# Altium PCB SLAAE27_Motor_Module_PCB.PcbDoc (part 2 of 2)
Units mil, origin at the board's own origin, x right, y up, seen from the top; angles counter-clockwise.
Board outline 2500 x 2000 mil, 4 copper layers (L1-Top Layer, L2-GND, L3-PWR, L4-Bottom Layer), stack 61.634 mil thick; 168 components, 85 nets, 418 pads, 206 vias.
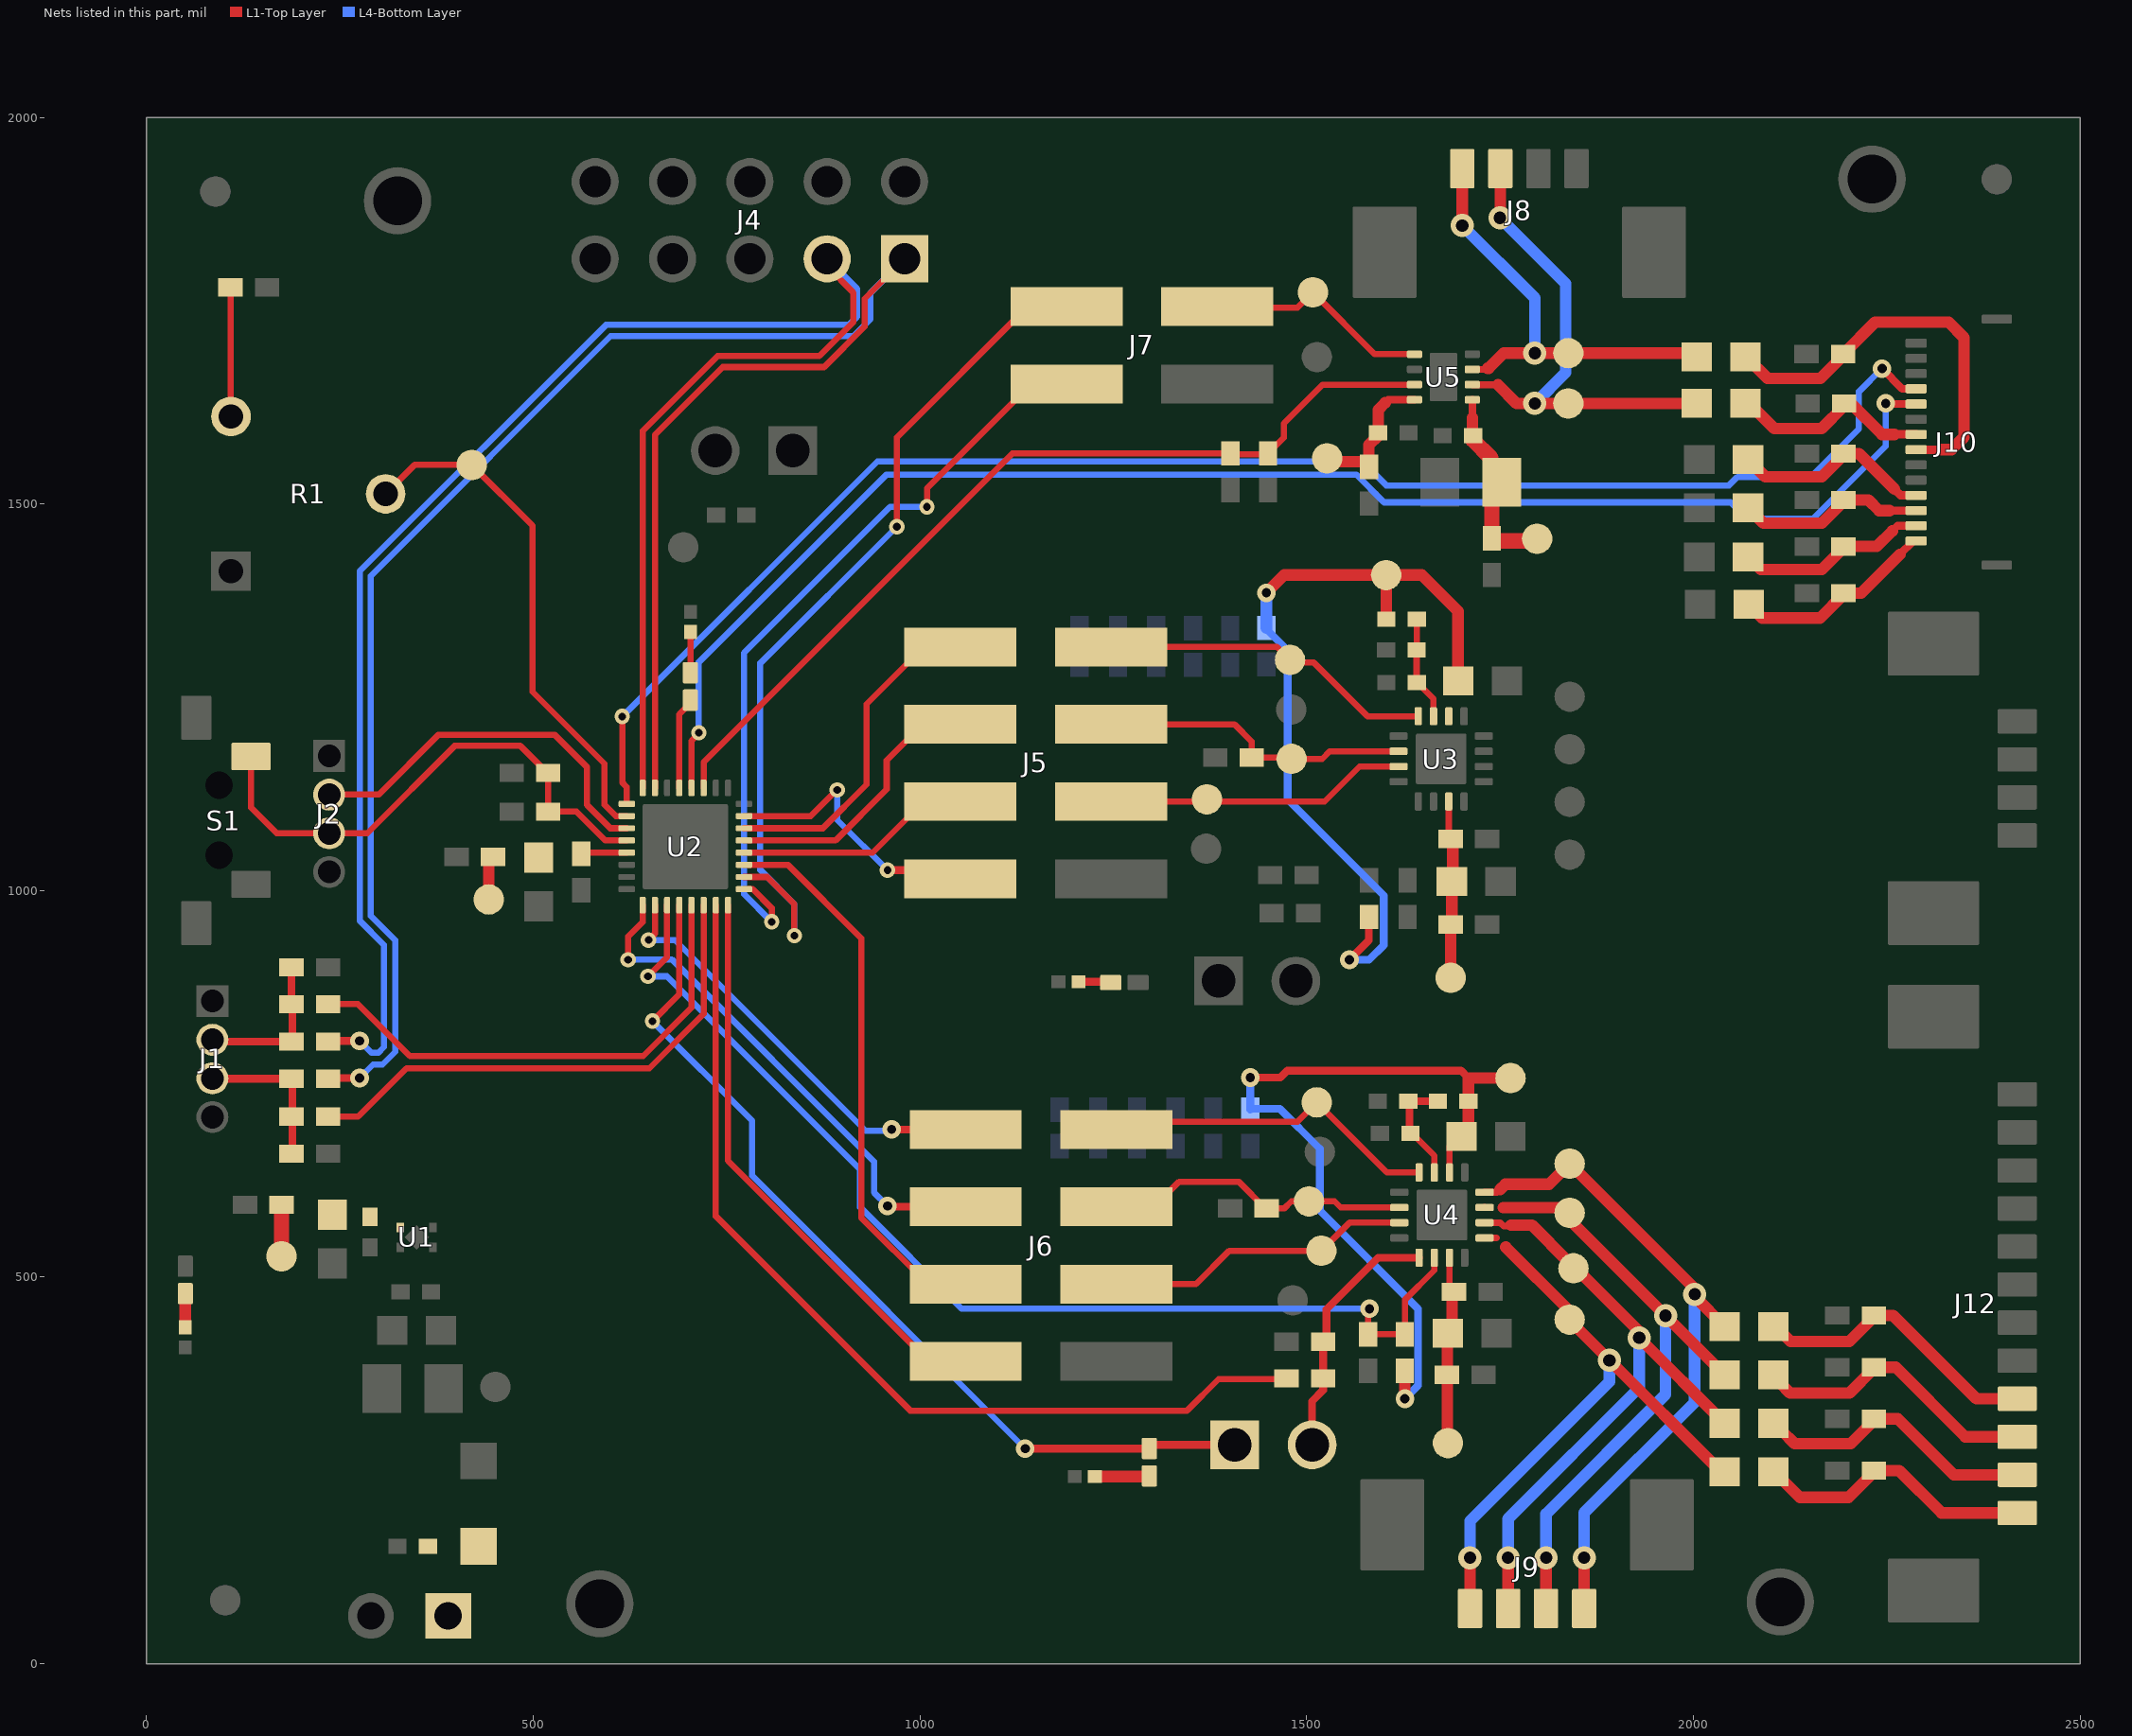
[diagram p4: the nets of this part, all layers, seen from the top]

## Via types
v1: diameter 24, hole 12, L1-Top Layer to L4-Bottom Layer, tented both sides, 151 vias
v2: diameter 30, hole 16, L1-Top Layer to L4-Bottom Layer, tented both sides, 20 vias
v3: diameter 20, hole 10, L1-Top Layer to L4-Bottom Layer, tented both sides, 18 vias
v4: diameter 19.68, hole 7.87, L1-Top Layer to L4-Bottom Layer, 17 vias

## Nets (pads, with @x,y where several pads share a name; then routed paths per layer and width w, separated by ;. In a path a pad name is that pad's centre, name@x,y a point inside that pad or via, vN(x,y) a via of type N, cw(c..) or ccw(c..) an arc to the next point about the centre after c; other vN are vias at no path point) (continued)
IN2/ENBL: IN2/ENBL.1 J7.3 U5.5 | length 319.4
  L1-Top Layer w8: J7.3@1363.44,1749 1368.44,1754 1488.23,1754 IN2/ENBL.1@1508,1773.77 1588.09,1693.67 U5.5@1639.4,1693.67
IRIS-M-A-N: IRIS-M-A-N.1 J8.1 L2.1 U5.3 | length 575.8
  L1-Top Layer w9: U5.3@1714.2,1673.99 1733.85,1673.99
  L1-Top Layer w15: v2(1701.18,1860) J8.1@1701.18,1933.74 ; 1733.85,1675.44 1735.3,1675.44 1754.86,1695 v2(1795,1695) IRIS-M-A-N.1@1838.3,1695 L2.1@2004.26,1695
  L4-Bottom Layer w15: v2(1701.18,1860) 1795,1766.18 v2(1795,1695)
IRIS-M-A-P: IRIS-M-A-P.1 J8.2 L1.1 U5.2 | length 655.7
  L1-Top Layer w9: U5.2@1714.2,1654.3 1714.39,1654.12 1747.27,1654.12
  L1-Top Layer w15: 1747.27,1654.12 1771.39,1630 v2(1795,1630) IRIS-M-A-P.1@1838.3,1630 L1.1@2004.26,1630 ; v2(1750,1870) 1750.39,1870.39 J8.2@1750.39,1933.74
  L4-Bottom Layer w15: v2(1750,1870) 1834.91,1785.09 1834.91,1669.91 v2(1795,1630)
IRIS_nSLEEP: R18.2 R20.1 U2.27 U5.7 | length 1165.5
  L1-Top Layer w8: U2.27@720.22,1132.65 720.22,1165.95 1119.52,1565.24 R18.2@1401.41,1565.24 ; R18.2@1406.97,1564.19 R20.1@1455.56,1564.19 ; R20.1@1450,1565.24 1470.5,1585.74 1470.5,1604.12 1520.68,1654.3 U5.7@1639.4,1654.3
M0_0: J5.7 M0_0.1 U3.8 | length 456.8
  L1-Top Layer w8: J5.7@1247,1315 1461.61,1315 M0_0.1@1478.42,1298.19 ; M0_0.1@1478.42,1294.67 1509.33,1294.67 1578.63,1225.37 U3.8@1644.36,1225.37
  L1-Top Layer w10: J5.7@1230,1314 J5.7@1246.81,1297.19
M0_1: J6.7 M0_1.1 U4.8 | length 444.2
  L1-Top Layer w8: J6.7@1254,690.87 1264.13,701 1488,701 M0_1.1@1513,726 ; M0_1.1@1512.5,726.5 M0_1.1@1513,726 ; U4.8@1645.35,635.28 1603.72,635.28 M0_1.1@1513,726
M1_0: J5.5 M1_0.1 R17.2 U3.10 | length 410.7
  L1-Top Layer w8: J5.5@1247,1215 1406.51,1215 1428.93,1192.58 R17.2@1428.93,1171.87 1477.38,1171.87 1479.7,1169.56 M1_0.1@1480.4,1170.25 1520.13,1170.25 1529.97,1180.1 U3.10@1618.77,1180.1 ; M1_0.1@1485,1182.65 M1_0.1@1487.55,1180.1
M1_1: J6.5 M1_1.1 R19.2 U4.10 | length 399.3
  L1-Top Layer w8: J6.5@1254,590.87 1302.59,590.87 1335.11,623.4 1412.11,623.4 R19.2@1446.78,588.73 ; R19.2@1448.26,588.73 1470.99,588.73 1480.27,598 M1_1.1@1503,598 1536,598 1544,590 U4.10@1619.76,590
MSP_DIR_0: J5.2 U2.23 | length 364
  L1-Top Layer w8: U2.23@772.39,1096.23 858.73,1096.23 892.5,1130 v3(893,1130)
  L1-Top Layer w10: v3(958,1026.31) 1040.81,1026.31 J5.2@1052.12,1015
  L4-Bottom Layer w8: v3(893,1130) 893,1091.31 v3(958,1026.31)
MSP_DIR_1: J6.2 U2.16 | length 745.5
  L1-Top Layer w8: U2.16@751.72,981.07 751.72,650.47 1011.31,390.87 J6.2@1059.12,390.87
MSP_IN1/PHASE: J7.2 U2.17 | length 1001.6
  L1-Top Layer w8: U2.17@772.39,1001.74 783.69,1001.74 808.32,977.12 v3(808.32,959.49) ; v3(1009,1496.31) 1009,1520 1144.18,1655.18 J7.2@1189.56,1655.18
  L4-Bottom Layer w8: v3(808.32,959.49) 772.39,995.42 772.39,1307.39 961.31,1496.31 v3(1009,1496.31)
MSP_IN2/ENBL: J7.4 U2.18 | length 1146.1
  L1-Top Layer w8: U2.18@772.39,1017.49 802.51,1017.49 837.58,982.42 v3(837.58,941.52) ; v3(970,1470.57) 970,1586 1139.18,1755.18 J7.4@1189.56,1755.18
  L4-Bottom Layer w8: v3(837.58,941.52) 837.58,982.42 793.45,1026.55 793.45,1294.02 v3(970,1470.57)
MSP_M0_0: J5.8 U2.22 | length 437.8
  L1-Top Layer w8: U2.22@772.39,1080.48 874.42,1080.48 931,1137.07 931,1241 1005,1315 J5.8@1052.12,1315
MSP_M0_1: J6.8 U2.10 | length 559.5
  L1-Top Layer w8: v3(649,935.93) 657.23,944.16 U2.10@657.23,981.07
  L1-Top Layer w10: v1(963.41,691.15) 963.69,690.87 J6.8@1059.12,690.87
  L4-Bottom Layer w8: v3(649,935.93) 683.07,935.93 929.68,689.32 v1@962,689.32
MSP_M1_0: J5.6 U2.21 | length 363.9
  L1-Top Layer w8: U2.21@772.39,1064.73 890.73,1064.73 956.92,1130.92 956.92,1168.28 1003.63,1215 J5.6@1052.12,1215
MSP_M1_1: J6.6 U2.9 | length 671.2
  L1-Top Layer w8: v3(622.57,910.43) 622.57,940.43 641.48,959.35 U2.9@641.48,981.07
  L1-Top Layer w10: v1(958,592) 959.13,590.87 J6.6@1059.12,590.87
  L4-Bottom Layer w8: v3(622.57,910.43) 623.01,910.87 679.13,910.87 940.5,649.5 940.5,609.5 v1(958,592)
MSP_STEP_0: J5.4 U2.20 | length 307.1
  L1-Top Layer w8: U2.20@772.39,1048.99 938.99,1048.99 1005,1115 J5.4@1052.12,1115
MSP_STEP_1: J6.4 U2.19 | length 723.2
  L1-Top Layer w8: U2.19@772.39,1033.24 829.05,1033.24 924,938.29 924,576.68 1009.81,490.87 J6.4@1059.12,490.87
Net3.3V_1: 3.3V.1 C1.1 C3.2 R4.1 U1.1 | length 68.3
  L1-Top Layer w20: 3.3V.1@174.47,526.92 174.47,589.65 R4.1@178.41,593.58
Net3.3V_MCU_1: 3.3V_MCU.1 C8.1 C9.2 R11.2 U2.5 | length 121.1
  L1-Top Layer w8: C9.2@557,1048.99 U2.5@620.81,1048.99
  L1-Top Layer w15: 3.3V_MCU.1@442.38,988.38 442.38,1037.76 R11.2@448,1043.38
NetC5_2: C5.2 D2.2 J3.1
NetC12_2: C12.2 R25.2 U5.8 VCC.1 | length 191.9
  L1-Top Layer w10: 1601.53,1630.7 1605.45,1634.62 U5.8@1639.4,1634.62
  L1-Top Layer w15: VCC.1@1525,1548.43 1531.19,1554.62 1573.72,1554.62 R25.2@1580.46,1547.88 1580.46,1576.27 1592.48,1588.28 1592.48,1621.64 1601.53,1630.7
NetC13_2: C13.2 R26.1 R31.2 U4.7 | length 149.5
  L1-Top Layer w8: C13.2@1633.54,688.49 1665.04,656.99 U4.7@1665.04,635.28
  L1-Top Layer w10: C13.2@1632.64,687.59 1633.54,688.49 C13.2@1634.37,689.32 ; C13.2@1638.02,685.67 1636.05,687.64 C13.2@1634.37,689.32 ; R31.2@1669.71,727.36 1632.82,727.36 1632.82,690.87 C13.2@1634.37,689.32
NetC14_2: C14.2 R27.1 R28.2 U3.7 | length 135.3
  L1-Top Layer w8: R28.2@1642.39,1351.14 1642.39,1311.3 R27.1@1642.14,1311.05 1642.14,1269.33 C14.2@1642.39,1269.07 1642.93,1269.07 1664.05,1247.95 U3.7@1664.05,1225.37
NetC15_1: C15.1 C18.2 R34.2 U5.1 VM_Iris.1 | length 254.1
  L1-Top Layer w10: C18.2@1714.2,1588.54 C18.2@1714.46,1588.28 ; 1714.2,1611.58 U5.1@1714.2,1634.62
  L1-Top Layer w15: C18.2@1714.2,1588.54 1714.2,1611.58
  L1-Top Layer w20: C18.2@1714.46,1588.28 1714.46,1583.23 1738.2,1559.48 1738.2,1510.64 1739.39,1509.45 R34.2@1739.39,1455.41 R34.2@1739.39,1452.05 ; R34.2@1738.01,1452.05 R34.2@1739.39,1452.05 ; VM_Iris.1@1797.92,1455 1794.96,1452.05 R34.2@1739.39,1452.05
NetC16_1: C16.1 C20.1 R32.2 U4.15 VM_TM.1 | length 243.7
  L1-Top Layer w8: C20.1@1684.72,477.75 U4.15@1684.72,525.04
  L1-Top Layer w15: VM_TM.1@1682.7,285.3 1681.78,286.23 1681.78,424.21 1688.15,430.59 C20.1@1688.15,478.69
NetC17_1: C17.1 C19.1 R33.2 U3.15 VM_Focus.1 | length 220.2
  L1-Top Layer w8: C19.1@1683.73,1076.34 U3.15@1683.73,1115.14
  L1-Top Layer w15: VM_Focus.1@1686.14,887.07 R33.2@1686.14,956.09 1687.71,957.67 C17.1@1687.71,1011.72 ; C17.1@1689.01,1011.72 1689.01,1064.13 C19.1@1691.61,1066.72
NetC23_1: C23.1 J10.7 L2.2 | length 530
  L1-Top Layer w11: J10.7@2288.07,1570.16 2320,1570.16
  L1-Top Layer w15: L2.2@2068.72,1690 2068.72,1689.46 2095.91,1662.27 2164.27,1662.27 2193.62,1691.62 C23.1@2193.62,1693.67 2234.95,1735 2330,1735 2350,1715 2350,1586.34 2333.82,1570.16 2320,1570.16
NetC24_2: C24.2 J10.1 L6.2 | length 264.4
  L1-Top Layer w10: 2267.03,1434.71 2284.37,1452.05 J10.1@2288.07,1452.05
  L1-Top Layer w15: L6.2@2071.5,1370 2089.2,1352.3 2163.73,1352.3 C24.2@2194,1382.57 ; C24.2@2194,1384.63 2216.95,1384.63 2267.03,1434.71
NetC25_2: C25.2 J10.2 L3.2 | length 248.9
  L1-Top Layer w10: 2257.2,1465 2263.93,1471.73 J10.2@2288.07,1471.73
  L1-Top Layer w15: L3.2@2070.7,1431.55 2087.24,1415 2166.06,1415 2194,1442.94 C25.2@2194,1445 2237.2,1445 2257.2,1465
NetC26_2: C26.2 J10.3 L4.2 | length 240
  L1-Top Layer w10: 2258.58,1491.42 J10.3@2288.07,1491.42
  L1-Top Layer w15: L4.2@2070.7,1495 2090.7,1475 2166.06,1475 2194,1502.94 C26.2@2194,1505 2226.52,1505 2240.1,1491.42 2253.62,1491.42
NetC27_1: C27.1 J10.4 L5.2 | length 262.6
  L1-Top Layer w11: 2260,1519.12 2268.02,1511.1 J10.4@2288.07,1511.1
  L1-Top Layer w15: L5.2@2070.7,1557.36 2093.05,1535 2166.06,1535 2194,1562.94 C27.1@2194,1565 2214.12,1565 2260,1519.12
NetC28_1: C28.1 J10.8 L1.2 | length 268.2
  L1-Top Layer w11: 2260,1589.84 J10.8@2288.07,1589.84
  L1-Top Layer w15: L1.2@2068.62,1635 2068.62,1633.37 2104.62,1597.37 2165.95,1597.37 2195,1626.42 C28.1@2195,1630 2203.81,1630 2243.97,1589.84 2260,1589.84
NetC29_1: C29.1 J12.12 L7.2 | length 352.7
  L1-Top Layer w15: L7.2@2114.14,238.74 2137.86,215.03 2200.75,215.03 2233.3,247.57 C29.1@2233.3,249.63 2266.27,249.63 2320.87,195.03 J12.12@2418.9,195.03
NetC30_1: C30.1 J12.11 L8.2 | length 354.9
  L1-Top Layer w15: L8.2@2114.14,301.45 2130.96,284.63 2203.57,284.63 2235.5,316.56 2264.44,316.56 2336.76,244.24 J12.11@2418.9,244.24
NetC31_2: C31.2 J12.10 L9.2 | length 364
  L1-Top Layer w15: L9.2@2112.47,362.53 2125,350 2201.87,350 2233.3,381.43 C31.2@2233.3,383.49 2261.51,383.49 2351.55,293.45 J12.10@2418.9,293.45
NetC32_2: C32.2 J12.9 L10.2 | length 368.3
  L1-Top Layer w15: L10.2@2114.96,427.42 2125.83,416.55 2201.55,416.55 2233.3,448.3 C32.2@2233.3,450.42 2258.32,450.42 2366.07,342.66 J12.9@2418.9,342.66
NetD1_1: D1.1 R2.1 | length 43.5
  L1-Top Layer w15: R2.1@50,435 D1.1@50,478.54
NetD3_1: D3.1 R14.1 | length 50.7
  L1-Top Layer w8: D3.1@703.12,1282.17 R14.1@703.12,1332.83
NetD4_1: D4.1 R15.1 | length 42.9
  L1-Top Layer w10: R15.1@1204.99,882.05 1245.52,882.05 D4.1@1246.57,881 D4.1@1246.57,880.07
NetD5_1: D5.1 R16.1 | length 61.3
  L1-Top Layer w15: R16.1@1235,242.07 1291.82,242.07 D5.1@1295,238.89
NetJ1_2: J1.2 R8.2 R9.1 R10.1 | length 199.8
  L1-Top Layer w10: J1.2@85,807 87.5,804.5 R8.2@187.38,804.5 ; R10.1@187.38,900.5 187.38,853.98 188.38,852.98 R8.2@188.38,804.5
NetJ1_3: J1.3 R5.1 R6.1 R7.2 | length 199.6
  L1-Top Layer w10: J1.3@85,756.5 R7.2@187.38,756.5 ; R5.1@188.38,659.5 188.38,707.27 188.61,707.5 188.61,756.27 R7.2@188.38,756.5
NetR1_3: R1.3 R3.1 | length 167.3
  L1-Top Layer w8: R3.1@108.38,1780 108.38,1613.62 R1.3@109,1613
PI_EN: J10.10 U2.28 | length 1959.1
  L1-Top Layer w8: U2.28@704.48,1132.65 704.48,1193.52 714,1203.05 v3(714,1204)
  L1-Top Layer w10: v1(2248.7,1630) 2249.49,1629.21 J10.10@2288.07,1629.21
  L4-Bottom Layer w8: v3(714,1204) 714,1295.23 956.77,1538 1564.06,1538 1600.06,1502 2048,1502 2068.87,1481.13 2155.13,1481.13 2248.7,1574.7 v1(2248.7,1630)
PI_INT: D3.2 U2.29 | length 120
  L1-Top Layer w8: U2.29@688.73,1132.65 688.73,1227.85 703.12,1242.24 D3.2@703.12,1246.73
PI_OUT: J10.11 U2.1 | length 2039.6
  L1-Top Layer w8: v3(615,1225) 615,1139.68 620.81,1133.86 U2.1@620.81,1111.98
  L1-Top Layer w10: v1(2243.97,1675.03) 2270.1,1648.9 J10.11@2288.07,1648.9
  L4-Bottom Layer w8: v3(615,1225) 945,1555 1572,1555 1603,1524 2046,1524 2057,1535 2152,1535 2214.12,1597.12 2214.12,1645.18 v1(2243.97,1675.03)
RST: C7.1 J2.3 R12.1 S1.3 U2.4 | length 692.4
  L1-Top Layer w8: S1.3@135,1173.33 135,1107.31 168.31,1074 J2.3@236,1074 285.32,1074 398.32,1187 483.33,1187 518.33,1152 C7.1@519.24,1152 R12.1@519.24,1102 556,1102 593.27,1064.73 U2.4@620.81,1064.73
RXD: R6.2 U2.14 | length 681.4
  L1-Top Layer w8: R6.2@234.62,707.5 273.5,707.5 336,770 650,770 720.22,840.22 U2.14@720.22,981.07
SCL: J4.1 R7.1 U2.31 | length 2504.1
  L1-Top Layer w8: U2.31@657.23,1132.65 657.23,1589.23 745,1677 876,1677 928.5,1729.5 928.5,1765.5 J4.1@980,1817
  L1-Top Layer w10: R7.1@234.62,757.5 v1(275.38,757.5)
  L4-Bottom Layer w8: v1(275.38,757.5) 292.88,775 305,775 321.5,791.5 321.5,935.5 289.92,967.08 289.92,1406.92 600,1717 914,1717 936,1739 936,1773 J4.1@980,1817
SDA: J4.3 R8.1 U2.32 | length 2469.1
  L1-Top Layer w8: U2.32@641.48,1132.65 641.48,1594.48 738.5,1691.5 869.99,1691.5 914,1735.51 914,1773 880,1807 J4.3@880,1817
  L1-Top Layer w10: R8.1@234.62,805.5 v1(275.38,805.5)
  L4-Bottom Layer w8: v1(275.38,805.5) 290.88,790 299.49,790 307,797.51 307,929.49 275.42,961.07 275.42,1412.93 593.99,1731.5 907.99,1731.5 918.49,1742 918.49,1778.51 J4.3@880,1817
SPEED_REF: R1.2 SPEED_REF.1 U2.2 | length 672.5
  L1-Top Layer w8: R1.2@309,1513 346.47,1550.47 SPEED_REF.1@420.47,1550.47 499,1471.94 499,1257 592,1164 592,1110.92 606.69,1096.23 U2.2@620.81,1096.23
STEP_0: J5.3 STEP_0.1 U3.11 | length 390.6
  L1-Top Layer w8: J5.3@1247,1115 1523.03,1115 1568.44,1160.41 U3.11@1618.77,1160.41
STEP_1: J6.3 STEP_1.1 U4.11 | length 398.7
  L1-Top Layer w8: J6.3@1254,490.87 1356.87,490.87 1400,534 STEP_1.1@1519,534 1555.31,570.31 U4.11@1619.76,570.31
TEST: J2.2 U2.3 | length 495.7
  L1-Top Layer w8: J2.2@236,1124 300,1124 377.5,1201.5 527.5,1201.5 569.5,1159.5 569.5,1110.5 599.52,1080.48 U2.3@620.81,1080.48
TM_A_N: J9.2 L9.1 TM_A_N.1 U4.3 | length 826.3
  L1-Top Layer w9: U4.3@1730,590 U4.3@1730.19,589.81
  L1-Top Layer w15: 1754.2,589.91 1828.24,589.91 TM_A_N.1@1840,578.15 ; J9.2@1809.61,71.26 v2(1809.61,136.98) ; TM_A_N.1@1840,583.15 TM_A_N.1@1840,578.15 ; L9.1@2040.5,373.56 v2(1964.07,450) 1840,574.07 TM_A_N.1@1840,578.15
  L4-Bottom Layer w15: v2(1809.61,136.98) 1809.61,193.61 1964.07,348.07 v2(1964.07,450)
TM_A_P: J9.1 L10.1 TM_A_P.1 U4.4 | length 879.5
  L1-Top Layer w9: U4.4@1730,609.68 1746.03,609.68
  L1-Top Layer w15: 1750,613 1757,620 1813.3,620 TM_A_P.1@1840,646.7 2001.7,485 v2(2001.7,477.75) 2001.7,474.75 L10.1@2040.5,435.95 ; J9.1@1858.82,71.26 v2(1858.82,136.98)
  L4-Bottom Layer w15: v2(1858.82,136.98) 1858.82,195.17 2001.7,338.05 v2(2001.7,477.75)
TM_B_N: J9.4 L7.1 TM_B_N.1 U4.1 | length 808.9
  L1-Top Layer w9: U4.1@1730,550.63 1745.41,550.63
  L1-Top Layer w15: J9.4@1711.18,71.26 v2(1711.18,136.98) ; 1757.43,538.61 1840,456.04 TM_B_N.1@1840,445.06 1840,443.85 v2(1891.42,392.43) L7.1@2030,253.85
  L4-Bottom Layer w15: v2(1711.18,136.98) 1711.18,184.44 1891.42,364.68 v2(1891.42,392.43)
TM_B_P: J9.3 L8.1 TM_B_P.1 U4.2 | length 843.6
  L1-Top Layer w9: U4.2@1730,570.31 1750.33,570.31 1754.68,565.96 1764.13,565.96
  L1-Top Layer w15: J9.3@1760.39,71.26 v2(1760.39,136.98) ; 1764.13,567.03 1791.26,567.03 1838.7,519.59 1840,519.59 1930,429.59 v2(1930,421.31) L8.1@2040.5,310.81
  L4-Bottom Layer w15: v2(1760.39,136.98) 1760.39,187.32 1930,356.93 v2(1930,421.31)
TM_EN: R22.1 U2.15 | length 1268.7
  L1-Top Layer w8: U2.15@735.97,981.07 735.97,578.77 987.43,327.31 1345.31,327.31 1386,368 1475.38,368 R22.1@1475.38,374
TM_EN_nFAULT: C11.1 JP3.2 R22.2 U4.13 | length 330.4
  L1-Top Layer w10: JP3.2@1507,283 1507,339.26 1521.24,353.5 C11.1@1521.24,416.55 1525.57,420.87 1525.57,458.3 1592.31,525.04 U4.13@1645.35,525.04
TM_nFAULT: D5.2 JP3.1 U2.12 | length 1181.1
  L1-Top Layer w8: v3(654,831) 688.73,865.73 U2.12@688.73,981.07
  L1-Top Layer w10: v1(1136,278) D5.2@1288,278 ; D5.2@1295,283 JP3.1@1407,283
  L4-Bottom Layer w8: v3(654,831) 783,702 783,631 v1(1136,278)
TM_nSLEEP: R23.1 R29.2 U2.11 U4.14 | length 1432.6
  L1-Top Layer w8: v3(648.25,889) 672.98,913.73 U2.11@672.98,981.07 ; v1(1581.22,459) 1580,459 1579.32,458.32 R23.1@1579.32,425.98 R29.2@1626.94,425.98 ; R29.2@1626.94,432.36 1626.94,470.59 1665.04,508.69 U4.14@1665.04,525.04
  L4-Bottom Layer w8: v3(648.25,889) 672.82,889 922.63,639.19 922.63,590.37 1054,459 v1(1581.22,459)
TXD: R9.2 U2.13 | length 656.1
  L1-Top Layer w8: R9.2@234.62,852.98 273.35,852.98 340.33,786 642,786 704.48,848.48 U2.13@704.48,981.07
VDD0: C21.1 R24.1 R28.1 R35.2 U3.6 VDD0.1 | length 1070.6
  L1-Top Layer w10: v1(1555.31,910.43) 1580.46,935.58 R24.1@1580.46,965.9
  L1-Top Layer w15: v1(1448,1385) 1471,1408 VDD0.1@1595.54,1408 ; VDD0.1@1602.77,1408 VDD0.1@1595.54,1408 ; R28.1@1603.02,1351.14 1603.02,1400.52 VDD0.1@1595.54,1408 ; C21.1@1695.82,1270.98 1695.82,1361.07 1648.72,1408.17 1595.38,1408.17 VDD0.1@1595.54,1408
  L4-Bottom Layer w10: R35.2@1447.25,1338.88 1475.38,1310.75 1475.38,1117.58 1599.69,993.27 1599.69,929.47 1580.65,910.43 v1(1555.31,910.43)
  L4-Bottom Layer w15: R35.2@1448,1339.62 v1(1448,1385)
VDD1: C22.1 R29.1 R31.1 R36.2 U4.6 VDD1.1 | length 1048.3
  L1-Top Layer w8: U4.6@1684.72,635.28 1684.72,669.28 C22.1@1708.99,693.55
  L1-Top Layer w10: v1(1427,758) 1466,758 1475,767 1699.44,767 1709.08,757.36 ; R31.1@1708.99,727.26 R31.1@1709.08,727.36
  L1-Top Layer w15: v1(1626.94,342.66) R29.1@1626.94,378.74 ; C22.1@1708.99,693.55 R31.1@1708.99,727.26 ; R31.1@1709.08,727.36 1709.08,757.36 VDD1.1@1763.53,757.36
  L4-Bottom Layer w10: R36.2@1427,716.62 R36.2@1427,717.62 ; v1(1427,758) R36.2@1427,717.62 ; v1(1626.94,342.66) 1644,359.72 1644,459 1517,586 1517,666 1465.38,717.62 R36.2@1427,717.62
pads on no net: FID1.1 FID2.1 FID3.1 FID4.1 FID5.1 FID6.1 H1.0 H2.0 H3.0 H4.0 J4.4 J4.5 J4.6 J4.7 J4.8 J4.9 J8.3 J8.4 J10.5 J10.6 J10.9 J10.13 J10.14 J12.1 J12.7 LBL1.0 S1. U5.9@1676.8,1646.43 U5.9@1676.8,1681.86

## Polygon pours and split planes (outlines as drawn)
TM_EN_nFAULT on L1-Top Layer "L1-TOP_LAYER_TM_EN_NFAULT_P052" (solid, pour order 52): 1504.52,410.23 1504.52,352.44 1473.26,321.18 1473.26,259.81 1486.78,246.28 1534.15,246.28 1546,258.13 1546,410.68 1546,455.3 1600.35,509.65 1648.68,509.65 1653,513.97 1653,535 1649,539 1645,539.09 1591.09,539.09 1504.52,452.52
3.3V on L1-Top Layer "L1-TOP_LAYER_3.3V_P086" (solid, pour order 86): 1593.45,1515.9 1553.05,1516.04 1550.47,1518.62 1518.62,1518.62 1510.17,1510.17 1510.17,1444.21 1524.01,1430.37 1582.37,1430.37 1593.45,1441.45
3.3V on L1-Top Layer "L1-TOP_LAYER_3.3V_P084" (solid, pour order 84): 413.16,1060.05 379.05,1060.17 373.23,1066 340.16,1066 326.31,1052.15 326.3,981.49 337.1,970.69 399.39,970.69 413.16,984.47 413.16,1055.97
5V on L1-Top Layer "L1-TOP_LAYER_5V_P082" (solid, pour order 82): 1722.74,1427.42 1722.59,1386.47 1716.77,1380.64 1716.77,1364 1739.5,1341.27 1783.18,1341.27 1814.09,1372.18 1814.09,1406.03 1792.7,1427.42
5V on L1-Top Layer "L1-TOP_LAYER_5V_P080" (solid, pour order 80): 1718.1,970 1717.97,933.01 1715.25,930.3 1715.25,907.44 1736.99,885.69 1794.3,885.69 1809.3,900.7 1809.31,957.97 1797.27,970
5V on L1-Top Layer "L1-TOP_LAYER_5V_P078" (solid, pour order 78): 1711.95,386 1711.83,351.89 1706,346.07 1706,319.95 1719.26,306.69 1781.31,306.69 1802.23,327.62 1802.23,360.77 1777,386 1716.03,386
FOCUS_EN_nFAULT on L1-Top Layer "L1-TOP_LAYER_FOCUS_EN_NFAULT_P054" (solid, pour order 54): 1482.01,936.01 1454,908 1454,862.63 1470.63,846 1512,846 1525.5,859.5 1525.5,1002.5 1525.5,1025.89 1599.36,1099.75 1647.69,1099.75 1652.01,1104.07 1652.01,1125.1 1648.01,1129.1 1644.01,1129.19 1579.81,1129.19 1482.01,1031.38
Net3.3V_MCU_1 on L1-Top Layer "L1-TOP_LAYER_NET3.3V_MCU_1_P060" (solid, pour order 60): 628.86,1056 582.73,1056 566.83,1071.89 440.89,1071.89 420,1051 420,976 432,964 456,964 464.01,972.01 464.01,1008.01 475,1019 538,1019 550,1031 573,1031 586,1044 630,1044 632,1046 632,1052.86
GND on L1-Top Layer "L1-TOP_LAYER_GND_P062" (solid, pour order 62): 592.5,1039 570.5,1017 550,1017 533,1000 489,1000 475,986 475,914.23 494.09,895.14 529.59,895.14 542,907.55 542,950 582.5,990.5 582.5,1007.5 603,1028 626.86,1028 630,1031.14 630,1037 628,1039
VDD0 on L1-Top Layer "L1-TOP_LAYER_VDD0_P036" (solid, pour order 36): 1675,1212.23 1675,1288.27 1680.73,1294 1712.08,1294 1718.17,1287.9 1718.17,1252.05 1714.74,1248.62 1698.15,1248.62 1691.26,1241.72 1691.26,1213.49 1690,1212.23
GND on L1-Top Layer "L1-TOP_LAYER_GND_P030" (solid, pour order 30): 1656.86,1700 1608.3,1700 1608.3,1732.01 1741.86,1732.01 1742.2,1701.89 1695.82,1701.89 1695.82,1571.75 1705,1562.57 1705,1459.4 1692.88,1447.29 1622.48,1447.29 1610.79,1458.98 1610.79,1590.79 1622.71,1602.71 1622.71,1603.8 1641.09,1603.8 1656.77,1619.47
GND on L1-Top Layer "L1-TOP_LAYER_GND_P058" (solid, pour order 58): 1698.51,649.06 1698.75,621.32 1738.64,621.32 1779.99,662.67 1809.98,662.67 1829,681.69 1829,713.43 1815.43,727 1752.9,727 1735.75,709.85 1735.75,667.15 1719.28,650.67 1700.13,650.67
VDD1 on L1-Top Layer "L1-TOP_LAYER_VDD1_P056" (solid, pour order 56): 1721.29,698.71 1721.29,716.14 1742.14,737 1777.62,737 1788,747.38 1788,769.66 1776.66,781 1700,781 1687.68,768.68 1687.68,725.47 1675.99,713.78 1675.99,622.14 1690.99,622.14 1692.25,623.4 1692.25,651.63 1699.15,658.52 1715.73,658.52 1721.29,664.08
GND on L1-Top Layer "L1-TOP_LAYER_GND_P038" (solid, pour order 38): 1697.52,1239.15 1697.76,1211.42 1737.65,1211.42 1779,1252.77 1808.98,1252.77 1816.4,1260.18 1816.4,1304.29 1798.71,1321.98 1743.93,1321.98 1734.76,1312.82 1734.76,1257.24 1718.29,1240.77 1699.14,1240.77
no net on L1-Top Layer "L1-Top Layer-No Net" (solid, pour order 48): 1717.7,1211.42
GND on L1-Top Layer "L1-TOP_LAYER_GND_P046" (solid, pour order 46): 1699.15,540.68 1699.15,509.84 1717.3,491.68 1717.3,464.9 1721.58,460.62 1721.58,402.75 1734.43,389.9 1811.84,389.9 1819.09,397.15 1819.09,442.61 1721.03,540.68
NetC16_1 on L1-Top Layer "L1-TOP_LAYER_NETC16_1_P044" (solid, pour order 44): 1677.27,536.03 1677.39,501.3 1661.76,485.67 1661.76,276.64 1673.4,265 1699.28,265 1704.41,270.13 1704.41,461.27 1704.41,494.31 1691.57,507.15 1691.57,535.5 1688.94,538.13 1679.37,538.13
GND on L1-Top Layer "L1-TOP_LAYER_GND_P042" (solid, pour order 42): 1698.15,1128.23 1698.15,1099.94 1716.31,1081.78 1716.31,1055 1720.59,1050.72 1720.59,992.85 1733.44,980 1810.85,980 1818.1,987.25 1818.1,1032.71 1722.58,1128.23
NetC17_1 on L1-Top Layer "L1-TOP_LAYER_NETC17_1_P040" (solid, pour order 40): 1676.28,1126.13 1676.4,1091.39 1666.89,1081.88 1666.89,875.08 1678.96,863 1700,863 1708.76,871.77 1708.76,1046.02 1703.42,1051.37 1703.42,1084.41 1690.58,1097.25 1690.58,1125.6 1687.95,1128.23 1678.38,1128.23
NetC12_2 on L1-Top Layer "L1-TOP_LAYER_NETC12_2_P034" (solid, pour order 34): 1532.64,1643.89 1500,1611.25 1500,1529.12 1510,1519.12 1510.88,1520 1591.52,1520 1606.15,1534.63 1606.15,1614.42 1618.55,1626.82 1650.57,1626.82 1650.57,1643.89
NetC15_1 on L1-Top Layer "L1-TOP_LAYER_NETC15_1_P032" (solid, pour order 32): 1704.41,1642.42 1703.42,1641.43 1703.42,1576.58 1720.16,1559.84 1720.16,1443.79 1728.95,1435 1818.36,1435 1826.31,1442.94 1826.31,1532.8 1729.01,1630.09 1729.01,1642.42
5V on L1-Top Layer "L1-TOP_LAYER_5V_P001" (solid, pour order 1): 357.15,333.43 357.15,230.36 369.48,218.58 449.01,218.58 476,245.57 476,606 461,621 367.78,621 367.78,523.71 349.28,505.2 349.28,371.13 357.15,363.26
GND on L1-Top Layer "L1-TOP_LAYER_GND_P002" (solid, pour order 2): 208.94,34.65 339.44,34.65 339.44,469.35 341.4,471.32 341.4,530.32 349.47,538.39 343.15,544.71 304.79,544.71 298.1,551.41 216.79,551.41 208.94,543.56 208.94,502.54
NetC5_2 on L1-Top Layer "L1-TOP_LAYER_NETC5_2_P028" (solid, pour order 28): 349.28,58.58 349.28,179.35 358.51,188.58 450.97,188.58 465.7,173.86 465.7,40.43 443.85,18.58 364.28,18.58 349.28,33.58
Net3.3V_1 on L1-Top Layer "L1-TOP_LAYER_NET3.3V_1_P004" (solid, pour order 4): 333.16,558.1 303.79,558.1 300.89,561 162,561 156.56,566.44 156.56,609.29 162.56,615.28 334.36,615.28 342.91,606.74 342.91,567.84
3.3V on L3-PWR "L3-PWR_3.3V_P024" (solid, remove dead copper, pour order 24): 1139.69,636.93 1324.63,452 1636.42,452 1694.7,510.28 1694.7,1442.28 1770.19,1518 2365,1518 2440.37,1593.37 2440.37,1922.1 2410.37,1952.1 183.21,1952.1 30.7,1799.59 30.7,81.3 94.41,17.59 2289.17,17.59 2440.37,168.79 2440.37,498.12 2422.5,516 2334.49,516 2310.37,491.89 2310.37,323.09 2310.37,304.48 2182.99,177.1 1284.9,177.1 1099.9,362.1 368.09,362.1 341.4,388.79 341.4,626.15 352.18,636.93
5V on L3-PWR "L3-PWR_5V_P068" (solid, remove dead copper, pour order 68): 1721,1410.03 1799.98,1489 1829.56,1489.65 2370.35,1489.65 2440,1420 2440,656.47 2273.23,489.7 2273.23,315 2168.23,210 1298.73,210 1113.73,395 402,395 370.33,426.67 370.33,604.82 385.51,620 1098.69,620 1293.04,425.66 1645.8,425.65 1721,500.85 1721,911.88
GND on L2-GND "L2-GND_GND_P026" (solid, pour order 26): 2445,1555 2445,536.99 2445,108 2372,35 105,35 35.33,104.67 35.33,1865.33 130,1960 2390,1960 2445,1905
GND on L4-Bottom Layer "L4-BOTTOM_LAYER_GND_P092" (solid, remove dead copper, pour order 92): 34,42 2455,41.99 2455,1583 2455,1957 34,1957

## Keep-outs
Keep-Out Layer:
  text ".Layer_Name" at -523,-958.49 h60

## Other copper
L1-Top Layer:
  region net 5V: 400.78,518.41 400.78,589.59 370.33,589.59 370.33,518.41
  region net IRIS-M-A-N: 1702.74,1679.95 1725.35,1679.94 1738.4,1679.94 1738.4,1669.97 1736.64,1668.21 1703.74,1668.21 1701.01,1670.94 1701.01,1678.21
  region net IRIS-M-A-P: 1702.93,1660.07 1725.54,1660.07 1743.19,1660.07 1743.19,1650.81 1740.71,1648.33 1703.93,1648.33 1701.19,1651.07 1701.19,1658.34
  region net TM_A_P: 1718.54,615.64 1741.15,615.64 1748.9,623.4 1753.19,623.4 1754.2,622.39 1754.2,605.28 1752.83,603.9 1719.54,603.9 1716.81,606.64 1716.81,613.91
  region net TM_A_N: 1718.54,595.96 1741.15,595.96 1756.85,595.95 1756.85,585.61 1755.46,584.22 1719.54,584.22 1716.81,586.95 1716.81,594.22
  region net TM_B_P: 1718.54,576.27 1762.02,576.27 1765,573.75 1765,562.02 1762.8,559.81 1755.39,559.81 1750.64,564.57 1720,564.57 1716.81,567.27 1716.81,574.54
  region net TM_B_N: 1739.23,544.85 1750.08,534 1753.36,534 1762.84,543.05 1749.3,556.58 1741.15,556.59 1718.54,556.59 1716.81,554.85 1716.81,547.58 1719.54,544.85
  region net FOCUS-M-A-N: 1738.24,1134.94 1744.19,1129 1746.61,1129 1754,1136.39 1754,1137.44 1744.76,1146.68 1740.15,1146.68 1717.55,1146.68 1715.81,1144.95 1715.81,1137.68 1718.55,1134.94
  region net FOCUS-M-A-P: 1717.55,1166.37 1758.38,1166.37 1760,1165 1760,1157.22 1754.78,1152 1748.37,1152 1745.33,1155.04 1718.55,1154.63 1715.81,1157.36 1715.81,1164.63
  region net FOCUS-M-B-N: 1717.55,1186.05 1740.15,1186.05 1753.21,1186.05 1753.21,1176.08 1751.45,1174.31 1718.55,1174.31 1715.81,1177.05 1715.81,1184.32
  region net FOCUS-M-B-P: 1717.55,1205.74 1740.15,1205.74 1747.91,1213.49 1752.2,1213.49 1753.21,1212.48 1753.21,1199.74 1747.47,1194 1718.55,1194 1715.81,1196.73 1715.81,1204
  region net GND: 272.71,513.67 349.28,513.67 349.28,546.43 344.44,551.54 272.71,551.54
  region net Net3.3V_1: 314.64,559.67 316.22,558.1 333.16,558.1 342.91,567.84 342.91,582.4 318.23,582.4 314.64,578.82
  text ".Layer_Name" at -523,-958.49 h60
L2-GND:
  text ".Layer_Name" at -520,-960.49 h60
L3-PWR:
  pour cut-out: 1779.87,1668.8 1779.87,1656.2 1805,1656.2 1805,1668.8
  text ".Layer_Name" at -523,-958.49 h60
L4-Bottom Layer:
  text ".Layer_Name" at -523,-958.49 h60

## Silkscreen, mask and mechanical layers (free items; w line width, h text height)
Top Overlay:
  lines w6: 1664.05,1312.22 1669.27,1317.44 1669.27,1328
  lines w8: 1332,1387 1332,1314 1387,1259 1437,1259 1451,1245 ; 1349,768 1349,711.61 1391.4,669.21 1483,669.21 ; 1499.73,1148 1507,1140.73 ; 1500,1812 1500,1873 1487,1886 ; 1526.63,613.91 1539,613.91 ; 1536.56,754.56 1545.3,745.82 1545.3,719.28 1567.58,697 1569.31,697 ; 1813.82,1430 1813.82,1411 1820.85,1403.97 ; 1850,1602.8 1850,1576 1861,1565 ; 1868,1706 1880,1718 ; 1869,450 1880,450 1890,440 ; 2031,1989 2031,1774 2031,1740 2041,1730 2128,1730 2135.23,1737.23 ; 2110,1728 2110,1358.13 2122.13,1346 2222,1346 2232,1356 2232,1737.52 2231.71,1737.23 2135.23,1737.23 ; 2141.5,1986.91 2139,1865.69 2135.23,1737.23 ; 2263,220 2255.58,212.58 2159.42,212.58 2148,224 2148,473 ; 1487,1886 1491.97,1890.97 1491.97,1981.03 1483,1990 1208,1990 1208,1898 1220,1886 1487,1886 ; 2148,473 2159,484 2242.42,484 2256,497.58 2256,676 2243.51,688.49 2149.17,688.49 2138,677.32 2138,483 2148,473 ; 1472.59,1674.41 1488.66,1658.34 1534.66,1658.34 1550,1673.68 1550,1799.98 1537.98,1812 1478.82,1812 1472.59,1805.77 1472.59,1674.41
  lines w10: -74.7,52.21 -54.88,-7.85 ; -69.02,1995.21 -48.84,2055.15 ; -64.88,-7.82 -44.88,-7.88 ; -58.84,2055.18 -38.84,2055.12 ; -53.02,627.78 -54.88,-7.85 ; -50.7,1419.53 -48.84,2055.15 ; -34.7,52.09 -54.88,-7.85 ; -29.02,1995.09 -48.84,2055.15 ; -5.04,2034 -4.96,2054 ; 54.92,2023.77 -5,2044 ; 55.08,2063.77 -5,2044 ; 850.12,2040.74 -5,2044 ; 1631.88,2037.76 2487,2034.5 ; 2426.92,2014.73 2487,2034.5 ; 2427.08,2054.73 2487,2034.5 ; 2486.96,2024.5 2487.04,2044.5
  text "2492.018 (mil)" at 859.99,2004.71 h60 r359.78
  text "Iris Motor" at 1667.34,1965 h30
  text "Focus Motor" at 2485,961.02 h30 r90
  text "2063.009 (mil)" at -17,637.67 h60 r89.83
  text "Tilt Motor" at 2484,138.51 h30 r90
  text "For evaluation only;" at 1004,105.55 h55
  text "not FCC approved for resale." at 931,50.55 h55
  text "GND" at 150,23 h30
  text "5V" at 453.91,20 h30
  text "Tilt Motor" at 1655.51,10 h30
  text ".Layer_Name" at -530,-945 h60
Bottom Overlay:
  text ".Layer_Name" at -523,-958.49 h60
Top Paste:
  text ".Layer_Name" at -523,-958.49 h60
Bottom Paste:
  text ".Layer_Name" at -523,-958.49 h60
Top Solder:
  circle w10: c93.66,1045.38 r14.67
  circle w10: c93.66,1135.93 r14.67
  text ".Layer_Name" at -523,-958.49 h60
  text ".Layer_Name" at -523,-958.49 h60
Bottom Solder:
  text ".Layer_Name" at -523,-958.49 h60
Drill Guide:
  text ".Layer_Name" at -523,-958.49 h60
M1 Board Outline:
  the board outline again, w10
M2 Board Dimensions:
  rectangle: -975,-500 -600,-375
  rectangle: -1100,-375 -975,-250
  lines w7: -1100,-375 -100,-375 ; -975,-500 -975,-250 ; -850,-500 -850,-250 ; -600,-500 -600,-250 ; -350,-500 -350,-250 ; -1100,-500 -1100,-250 -100,-250 -100,-500 -1100,-500
M3 3D STEP Top:
  text ".Layer_Name" at -523,-958.49 h60
M4 3D STEP Bottom:
  text ".Layer_Name" at -523,-958.49 h60
M5 Assembly Top:
  lines w10: -1392,-1030.17 5208,-1030.17 ; -1392,-826.83 5210,-826.83 ; -1392,-623.5 -1392,-1233.5 2613,-1233.5 5210,-1233.5 5210,-623.5 -1391.5,-623.5 -1391.5,-1233.5 184,-1233.5 ; 1073,-1233.5 1073,-623.5 ; 2340,-826.83 2340,-623.5 ; 3180,-826.83 3180,-623.5 ; 3802,-1240 3802,-1037.17
  text "COMPONENTS MARKED 'DNP' SHOULD NOT BE POPULATED." at 53.5,-418.5 h60
  text "ASSEMBLY VARIANT:" at 53,-534 h60
  text ".VariantName" at 1089,-534 h60
  text "PCB VIEWED FROM TOP SIDE" at -1328.5,-755.67 h60
  text "BOARD #:" at 1148,-755.67 h60
  text ".PRJ_Number" at 1693.5,-755.67 h60
  text "REV:" at 2538,-755.67 h60
  text ".PCB_Rev" at 2829.5,-755.67 h60
  text "SVN REV:" at 3376,-755.67 h60
  text ".VersionControl_RevNumber" at 3882,-755.67 h60
  text "TID #:" at 1148,-959 h60
  text ".TID" at 1693.5,-959 h60
  text "PLOT NAME =" at -1328.5,-1164.34 h60
  text ".plot_File_Name" at -523,-1164.34 h60
  text "GENERATED    :" at 1150,-1164.34 h60
  text ".Print_Date" at 2019.5,-1164.34 h60
  text ".Print_Time" at 2748.5,-1164.34 h60
  text "TEXAS INSTRUMENTS" at 4013,-1164.34 h60
M6 Assembly Bottom:
  lines w10: -1392.5,-827.33 5209.5,-827.33 ; -1390.5,-1030.67 5209.5,-1030.67 ; 15.5,-1240.5 15.5,-1037.67 ; 637.5,-827.33 637.5,-624 ; 1477.5,-827.33 1477.5,-624 ; 2744.5,-1234 2744.5,-624 ; 3633.5,-1234 5209,-1234 5209,-624 -1392.5,-624 -1392.5,-1234 1204.5,-1234 5209.5,-1234 5209.5,-624
  text "COMPONENTS MARKED 'DNP' SHOULD NOT BE POPULATED." at 5002,-418 h60
  text ".VariantName" at 3958,-534 h60
  text "ASSEMBLY VARIANT:" at 4997,-534 h60
  text ".VersionControl_RevNumber" at -64.5,-756.17 h60
  text "SVN REV:" at 441.5,-756.17 h60
  text ".PCB_Rev" at 988,-756.17 h60
  text "REV:" at 1279.5,-756.17 h60
  text ".PRJ_Number" at 2124,-756.17 h60
  text "BOARD #:" at 2669.5,-756.17 h60
  text "PCB VIEWED FROM BOTTOM SIDE" at 5146,-756.17 h60
  text ".TID" at 2124,-959.5 h60
  text "TID #:" at 2669.5,-959.5 h60
  text "TEXAS INSTRUMENTS" at -195.5,-1164.84 h60
  text ".Print_Time" at 1069,-1164.84 h60
  text ".Print_Date" at 1798,-1164.84 h60
  text "GENERATED    :" at 2667.5,-1164.84 h60
  text ".plot_File_Name" at 4340.5,-1164.84 h60
  text "PLOT NAME =" at 5146,-1164.84 h60
M9 Title Sheet:
  drawing of 57 lines, arcs and shapes, not listed
  text "1" at -360.16,7936.5 h70
  text "2" at 2135.5,7936.5 h70
  text "3" at 4624.84,7936.5 h70
  text "4" at 7131.51,7936.5 h70
  text "5" at 9630.5,7936.5 h70
  text "6" at 12135.5,7936.5 h70
  text "A" at -1516.5,6793.5 h70
  text "A" at 13283.5,6793.5 h70
  text "B" at -1516.5,4413.5 h70
  text "B" at 13283.5,4413.5 h70
  text "C" at -1516.5,2038.5 h70
  text "C" at 13283.5,2038.5 h70
  text "PROJECT TITLE:" at 10243.5,177.5 h45
  text ".PRJ_Title" at 10293.5,44.17 h70
  text "DESIGNED FOR:" at 10243.5,-123.5 h45
  text ".PRJ_Customer" at 10293.5,-263.5 h70
  text "D" at -1516.5,-331.5 h70
  text "D" at 13283.5,-331.5 h70
  text "FILE NAME:" at 10243.5,-423.5 h45
  text ".PCB_File_Name_No_Path" at 10293.5,-543.5 h70
  text "Texas Instruments (TI) and/or its licensors do not warrant the accuracy or completeness of this specification" at 5274,-705.34 h45
  text "ENGINEER:" at 10243.5,-713.5 h45
  text "LAYOUT BY:" at 11748.5,-713.5 h45
  text "or any information contained therein. TI and/or its licensors do not warrant that this design will meet" at 5229.01,-818 h45
  text ".PRJ_Engineer" at 10293.5,-868.49 h70
  text ".PCB_Layout" at 11799,-868.49 h70
  text "the specifications, will be suitable for your application or fit for any particular purpose, or will operate in" at 5229.01,-930.67 h45
  text "ALTIUM DESIGNER VERSION:" at 11748.5,-1023.5 h45
  text "an implementation. TI and/or its licensors do not warrant that the design is production worthy. You should" at 5229.01,-1043.33 h45
  text "completely validate and test your design implementation to confirm the system functionality for your application." at 5274,-1156 h45
  text ".print_Scale" at 10293.5,-1156.83 h70
  text ".Application_BuildNumber" at 11799,-1156.83 h70
  text "1" at -360.16,-1363.5 h70
  text "2" at 2135.5,-1363.5 h70
  text "3" at 4624.84,-1363.5 h70
  text "4" at 7131.51,-1363.5 h70
  text "5" at 9630.5,-1363.5 h70
  text "6" at 12135.5,-1363.5 h70
M10 Fab Notes:
  drawing of 189 lines, arcs and shapes, not listed
  text "DESIGN INFORMATION" at 11282.02,6256.17 h60
  text "MIN. TRACK WIDTH:" at 10637.46,6124.05 h60
  text "8" at 11733.7,6124.05 h60
  text "MIL" at 11888.46,6124.05 h60
  text "4.37 MIL" at 11649,6004 h60
  text "MIN. CLEARANCE:" at 10637.46,5999.92 h60
  text "MIN. VIA PAD SIZE:" at 10637.46,5875.8 h60
  text "20" at 11703.71,5875.8 h60
  text "MIL" at 11888.46,5875.8 h60
  text "0.05mm (2MIL)" at 11332.46,5745.9 h60
  text "MINIMUM ANNULAR RING" at 10308.23,5737.67 h60
  text "EXTERNAL" at 12040.46,5737.67 h60
  text "PER" at 10508.23,5627.55 h60
  text "IPC-D-275 CLASS 2 LEVEL C" at 10728.23,5627.54 h60
  text "MIL, HOLES" at 12216.46,5527.07 h60
  text "+/-" at 11824,5518.48 h60
  text "+/-" at 12678,5518.48 h60
  text "REGISTRATION TOLERANCES:" at 10308.23,5517.42 h60
  text "METAL" at 11508,5517.42 h60
  text "5" at 12084.2,5517.42 h60
  text "3" at 12917.2,5517.42 h60
  text "MIL" at 13033.46,5517.42 h60
  text "HOLE SIZE TOLERANCE (UNLESS OTHERWISE SPECIFIED):" at 10308.23,5419.1 h60
  text "+/-" at 12678,5416.23 h60
  text "3" at 12917.2,5415.17 h60
  text "MIL" at 13033.46,5415.17 h60
  text "MATERIAL:" at 10233.46,5277.52 h60
  text "FR-4 High Tg" at 11219.9,5149 h60
  text "X" at 11075.46,5141.01 h60
  text "FR-408" at 10654.46,5136.49 h60
  text "OTHER" at 12142.46,5136.49 h60
  text "62 MIL (1.6mm) +/-10%" at 10974.56,4993.46 h60
  text "X" at 10854.46,4991.01 h60
  text "THICKNESS:" at 10308.23,4985.24 h60
  text "OTHER" at 12259.46,4985.24 h60
  text "TOLERANCE:" at 10308.23,4846.92 h60
  text "X" at 11156.46,4846.92 h60
  text "ANSI IPC-6012 TYPE 3 CLASS 2" at 11334.48,4846.92 h60
  text "OTHER +/-" at 11334.46,4702.73 h60
  text "BOW & TWIST:" at 10308.23,4557.54 h60
  text "X" at 11156.46,4557.54 h60
  text "ANSI IPC-6012 TYPE 3 CLASS 2" at 11334.48,4557.54 h60
  text "OTHER +/-" at 11334.46,4410.85 h60
  text "DRILLING:" at 10233.46,4280.23 h60
  text "NC_DRILL FILES" at 11994.46,4175.04 h60
  text "REFERENCE:" at 10308.23,4171.1 h60
  text "X" at 10965.46,4171.01 h60
  text "AS SHOWN" at 11143.46,4171.1 h60
  text "X" at 11866.46,4171.1 h60
  text "OTHER" at 12292.46,4028.85 h60
  text "PTH COPPER THICKNESS:" at 10307.91,4025.32 h60
  text "X" at 11447.14,4025.32 h60
  text "20-30 um" at 11575.14,4025.32 h60
  text "BOARD FINISH:" at 10233.46,3877.73 h60
  text "SILKSCREEN:" at 10388.68,3767.6 h60
  text "X" at 11346.46,3767.6 h60
  text "TOP" at 11463.46,3767.6 h60
  text "X" at 11856.46,3767.6 h60
  text "BOTTOM" at 11974.46,3767.6 h60
  text "SILKSCREEN COLOR:" at 10388.68,3612.41 h60
  text "X" at 11345.46,3612.41 h60
  text "WHITE" at 11463.46,3612.41 h60
  text "OTHER" at 11974.46,3612.41 h60
  text "X" at 11476.46,3468.96 h60
  text "GREEN" at 11594.46,3468.96 h60
  text "OTHER" at 12212.46,3468.96 h60
  text "SOLDER RESIST COLOR:" at 10388.68,3462.1 h60
  text "X" at 11476.46,3314.71 h60
  text "MATTE" at 11594.46,3314.71 h60
  text "SEMI-GLOSS" at 12212,3314.07 h60
  text "IMMERSION GOLD (ENIG)" at 11294.46,3141.94 h60
  text "ENEPIG" at 12632,3134.72 h60
  text "SURFACE FINISH:" at 10233.46,3133.72 h60
  text "X" at 11116.46,3133.72 h60
  text "IMM. TIN/SILVER OR EQUIV" at 10563,2996.4 h60
  text "OTHER" at 11994.46,2992.47 h60
  text "ARRAY/PANEL:" at 10233.46,2837.09 h60
  text "X" at 11110,2828.87 h60
  text "CUT AND TRIM PER M1 BOARD OUTLINE" at 11294.46,2828.87 h60
  text "N.C. ROUTE" at 11294.46,2692.9 h60
  text "V. SCORE" at 12160.46,2692.9 h60
  text "CERTIFICATION:" at 10233.46,2563.77 h60
  text "MATERIALS AND WORKMANSHIP FOR ALL PCBS" at 10958.46,2563.77 h60
  text "TO MEET OR EXCEED THE REQUIREMENTS OF:" at 10958.46,2469.71 h60
  text "X" at 10595.97,2341.08 h60
  text "ANSI IPC-A-600F CLASS ->" at 10723.96,2341.08 h60
  text "X" at 12371.97,2341.08 h60
  text "2" at 12481.96,2341.08 h60
  text "1" at 12166.96,2339.58 h60
  text "3" at 12835.96,2339.58 h60
  text "X" at 11407.97,2193.39 h60
  text "RoHS" at 11535.96,2193.39 h60
  text "OTHER" at 12180.36,2193.39 h60
  text "PER ORDER" at 12577.42,2193.39 h60
  text "ALL BOARDS MUST MEET OR EXCEED UL94-V0 REQUIREMENTS." at 10261,2039.57 h60
  text "PCB MUST BEAR THE UL94V-0 UL REGISTERED MATERIAL ID NUMBER" at 10261,1923.5 h60
  text "ADDITIONAL REQUIREMENTS:" at 10233.46,1754.08 h60
  text "MICROSECTION:" at 10308.23,1646.95 h60
  text "YES" at 11213.96,1646.95 h60
  text "REQUIRED" at 12075.46,1502.62 h60
  text "BARE BOARD ELEC. TEST:" at 10308.23,1499.76 h60
  text "NONE" at 11613.96,1499.76 h60
  text "X" at 11957.46,1499.76 h60
  text "PER ORDER" at 12667.46,1499.76 h60
  text "XX MIL VIAS REQUIRE NON-CONDUCTIVE FILL AND PLANARIZE" at 10476.38,1294.82 h59
  text "XX MIL VIAS REQUIRE CONDUCTIVE FILL AND PLANARIZE" at 10484.38,1190.84 h60
  text "1. THIS IS NOT IMPEDANCE CONTROL BOARD." at 3929,1118 h60
  text "OUTER XX MIL TRACES REQUIRE 50 OHM SINGLE-ENDED IMPEDANCE" at 10483.39,1027.46 h58
  text "2. ALL VIA'S ARE TENTED EXCEPT ONPAD VIAS." at 3929,978 h60
  text "3. SAME SIZE SOLDER MASK IS USED FOR SOME COMPONENTS, VENDOR CAN MODIFY AS PER FAB CAPABILITIES" at 3929,862 h60
  text "LAYER 2 & 3 (INNER LAYERS) XX MIL WIDE, XX MIL SPACE / TRACES REQUIRE 100 OHM DIFFERENTIAL IMPEDANCE" at 10475.39,791.74 h60
M11 Gerber Information:
  lines w10: -1392,-1030.17 5208,-1030.17 ; -1392,-826.83 5210,-826.83 ; -1392,-623.5 -1392,-1233.5 2613,-1233.5 5210,-1233.5 5210,-623.5 -1391.5,-623.5 -1391.5,-1233.5 184,-1233.5 ; 1073,-1233.5 1073,-623.5 ; 2340,-826.83 2340,-623.5 ; 3180,-826.83 3180,-623.5 ; 3802,-1240 3802,-1037.17
  text "ALL ARTWORK VIEWED FROM TOP SIDE" at -1328.5,-755.67 h60
  text "REV:" at 2538,-755.67 h60
  text ".PCB_Rev" at 2829.5,-755.67 h60
  text "SVN REV:" at 3376,-755.67 h60
  text ".VersionControl_RevNumber" at 3882,-755.67 h60
  text "BOARD #:" at 1097,-760 h47
  text ".PRJ_Number" at 1460,-761 h47
  text "LAYER NAME =" at -1328.5,-958.49 h60
  text "TID #:" at 1148,-959 h60
  text ".TID" at 1693.5,-959 h60
  text "PLOT NAME =" at -1328.5,-1164.34 h60
  text ".plot_File_Name" at -523,-1164.34 h60
  text "GENERATED    :" at 1150,-1164.34 h60
  text ".Print_Date" at 2019.5,-1164.34 h60
  text ".Print_Time" at 2748.5,-1164.34 h60
  text "TEXAS INSTRUMENTS" at 4013,-1164.34 h60
M12 Stackup:
  drawing of 295 lines, arcs and shapes, not listed
  text "Layer" at 5136.09,6186.5 h60
  text "Name" at 5546,6186.5 h60
  text "Material" at 6535.72,6186.5 h60
  text "Thickness" at 7395.49,6186.5 h60
  text "Constant" at 8045.33,6186.5 h60
  text "Board Layer Stack" at 8615.19,6186.5 h60
  text "1" at 5136.09,6066.5 h60
  text "Top Overlay" at 5546,6066.5 h60
  text "2" at 5136.09,5946.5 h60
  text "Top Solder" at 5546,5946.5 h60
  text "Solder Resist" at 6535.72,5946.5 h60
  text "0.40mil" at 7395.49,5946.5 h60
  text "3.5" at 8045.33,5946.5 h60
  text "3" at 5136.09,5826.5 h60
  text "L1-Top Layer" at 5546,5826.5 h60
  text "Copper" at 6535.72,5826.5 h60
  text "1.40mil" at 7395.49,5826.5 h60
  text "4" at 5136.09,5706.5 h60
  text "Dielectric 3" at 5546,5706.5 h60
  text "FR-4 High Tg" at 6535.72,5706.5 h60
  text "4.00mil" at 7395.49,5706.5 h60
  text "4.2" at 8045.33,5706.5 h60
  text "5" at 5136.09,5586.5 h60
  text "L2-GND" at 5546,5586.5 h60
  text "Copper" at 6535.72,5586.5 h60
  text "1.42mil" at 7395.49,5586.5 h60
  text "6" at 5136.09,5466.5 h60
  text "Dielectric 2" at 5546,5466.5 h60
  text "FR-4 High Tg" at 6535.72,5466.5 h60
  text "48.00mil" at 7395.49,5466.5 h60
  text "4.2" at 8045.33,5466.5 h60
  text "7" at 5136.09,5346.5 h60
  text "L3-PWR" at 5546,5346.5 h60
  text "Copper" at 6535.72,5346.5 h60
  text "1.42mil" at 7395.49,5346.5 h60
  text "8" at 5136.09,5226.5 h60
  text "Dielectric1" at 5546,5226.5 h60
  text "FR-4 High Tg" at 6535.72,5226.5 h60
  text "4.00mil" at 7395.49,5226.5 h60
  text "4.2" at 8045.33,5226.5 h60
  text "9" at 5136.09,5106.5 h60
  text "L4-Bottom Layer" at 5546,5106.5 h60
  text "Copper" at 6535.72,5106.5 h60
  text "1.40mil" at 7395.49,5106.5 h60
  text "10" at 5136.09,4986.5 h60
  text "Bottom Solder" at 5546,4986.5 h60
  text "Solder Resist" at 6535.72,4986.5 h60
  text "0.40mil" at 7395.49,4986.5 h60
  text "3.5" at 8045.33,4986.5 h60
  text "11" at 5136.09,4866.5 h60
  text "Bottom Overlay" at 5546,4866.5 h60
M13 Component Bodies Top:
  text ".Layer_Name" at -523,-958.49 h60
M14 Component Bodies Bottom:
  text ".Layer_Name" at -523,-958.49 h60
M15 Courtyards Top:
  text ".Layer_Name" at -523,-958.49 h60
M16 Courtyards Bottom:
  text ".Layer_Name" at -523,-958.49 h60
Drill Drawing:
  circle w10: c4903.62,3532.3 r16.67
  circle w10: c4903.62,3532.3 r27.78
  circle w10: c4903.62,3032.33 r27.78
  lines w10: 4875.84,2393.48 4889.73,2393.48 4889.73,2379.59 4917.51,2379.59 4917.51,2393.48 4931.39,2393.48 4931.39,2421.26 4917.51,2421.26 4917.51,2435.14 4889.73,2435.14 4889.73,2421.26 4875.84,2421.26 4875.84,2393.48 ; 4875.84,2504.58 4931.39,2504.58 4931.39,2560.14 4875.84,2560.14 4875.84,2504.58 ; 4875.84,2643.46 4889.73,2643.46 4903.62,2629.58 4917.51,2643.46 4931.39,2643.46 4917.51,2657.35 4931.39,2671.24 4917.51,2671.24 4903.62,2685.13 4889.73,2671.24 4875.84,2671.24 4889.73,2657.35 4875.84,2643.46 ; 4875.84,2754.57 4903.62,2768.46 4931.39,2754.57 4917.51,2782.34 4931.39,2810.12 4903.62,2796.23 4875.84,2810.12 4889.73,2782.34 4875.84,2754.57 ; 4875.84,2935.11 4931.39,2935.11 4903.62,2879.56 4875.84,2935.11 ; 4875.84,3185.1 4931.39,3185.1 4903.62,3129.54 4875.84,3185.1 ; 4875.84,3254.54 4931.39,3254.54 4931.39,3310.09 4875.84,3310.09 4875.84,3254.54 ; 4875.84,3407.3 4903.62,3379.53 4931.39,3407.3 4903.62,3435.08 4875.84,3407.3 ; 4875.84,3629.51 4875.84,3643.4 4889.73,3657.29 4875.84,3671.18 4875.84,3685.06 4889.73,3685.06 4903.62,3671.18 4917.51,3685.06 4931.39,3685.06 4931.39,3671.18 4917.51,3657.29 4931.39,3643.4 4931.39,3629.51 4917.51,3629.51 4903.62,3643.4 4889.73,3629.51 4875.84,3629.51 ; 4886.95,3173.99 4920.28,3173.99 4903.62,3140.65 4886.95,3173.99 ; 4886.95,3265.65 4920.28,3265.65 4920.28,3298.98 4886.95,3298.98 4886.95,3265.65
  lines w12: 4186,2342.09 7929.71,2342.09 ; 4186,3717.01 7929.71,3717.01 ; 4862.99,2217.1 4862.99,3842 ; 5502.49,2217.1 5502.49,3842 ; 5836.06,2217.1 5836.06,3842 ; 6096.43,2217.1 6096.43,3842 ; 6473.35,2217.1 6473.35,3842 ; 7004.93,2217.1 7004.93,3842 ; 4186,2217.1 7929.71,2217.1 7929.71,3842 4186,3842 4186,2217.1
  text "Finished Hole Size" at 4261,3754.5 h72.32
  text "Symbol" at 4900.49,3754.5 h72.32
  text "Quantity" at 5539.99,3754.5 h72.32
  text "Plated" at 5873.55,3754.5 h72.32
  text "Hole Type" at 6133.93,3754.5 h72.32
  text "Hole Tolerance" at 6510.84,3754.5 h72.32
  text "Drill Layer Pair" at 7042.43,3754.5 h72.32
  text "35.43mil (0.900mm)" at 4261,3629.51 h60.27
  text "2" at 5539.99,3629.51 h60.27
  text "NPTH" at 5873.55,3629.51 h60.27
  text "Round" at 6133.93,3629.51 h60.27
  text "L1-Top Layer - L4-Bottom Layer" at 7042.43,3629.51 h60.27
  text "7.87mil (0.200mm)" at 4261,3504.52 h60.27
  text "17" at 5539.99,3504.52 h60.27
  text "PTH" at 5873.55,3504.52 h60.27
  text "Round" at 6133.93,3504.52 h60.27
  text "L1-Top Layer - L4-Bottom Layer" at 7042.43,3504.52 h60.27
  text "10.00mil (0.254mm)" at 4261,3379.53 h60.27
  text "18" at 5539.99,3379.53 h60.27
  text "PTH" at 5873.55,3379.53 h60.27
  text "Round" at 6133.93,3379.53 h60.27
  text "L1-Top Layer - L4-Bottom Layer" at 7042.43,3379.53 h60.27
  text "12.00mil (0.305mm)" at 4261,3254.54 h60.27
  text "151" at 5539.99,3254.54 h60.27
  text "PTH" at 5873.55,3254.54 h60.27
  text "Round" at 6133.93,3254.54 h60.27
  text "L1-Top Layer - L4-Bottom Layer" at 7042.43,3254.54 h60.27
  text "16.00mil (0.406mm)" at 4261,3129.54 h60.27
  text "20" at 5539.99,3129.54 h60.27
  text "PTH" at 5873.55,3129.54 h60.27
  text "Round" at 6133.93,3129.54 h60.27
  text "L1-Top Layer - L4-Bottom Layer" at 7042.43,3129.54 h60.27
  text "29.53mil (0.750mm)" at 4261,3004.55 h60.27
  text "8" at 5539.99,3004.55 h60.27
  text "PTH" at 5873.55,3004.55 h60.27
  text "Round" at 6133.93,3004.55 h60.27
  text "L1-Top Layer - L4-Bottom Layer" at 7042.43,3004.55 h60.27
  text "31.50mil (0.800mm)" at 4261,2879.56 h60.27
  text "3" at 5539.99,2879.56 h60.27
  text "PTH" at 5873.55,2879.56 h60.27
  text "Round" at 6133.93,2879.56 h60.27
  text "L1-Top Layer - L4-Bottom Layer" at 7042.43,2879.56 h60.27
  text "35.43mil (0.900mm)" at 4261,2754.57 h60.27
  text "2" at 5539.99,2754.57 h60.27
  text "PTH" at 5873.55,2754.57 h60.27
  text "Round" at 6133.93,2754.57 h60.27
  text "L1-Top Layer - L4-Bottom Layer" at 7042.43,2754.57 h60.27
  text "40.16mil (1.020mm)" at 4261,2629.58 h60.27
  text "10" at 5539.99,2629.58 h60.27
  text "PTH" at 5873.55,2629.58 h60.27
  text "Round" at 6133.93,2629.58 h60.27
  text "L1-Top Layer - L4-Bottom Layer" at 7042.43,2629.58 h60.27
  text "43.31mil (1.100mm)" at 4261,2504.58 h60.27
  text "6" at 5539.99,2504.58 h60.27
  text "PTH" at 5873.55,2504.58 h60.27
  text "Round" at 6133.93,2504.58 h60.27
  text "L1-Top Layer - L4-Bottom Layer" at 7042.43,2504.58 h60.27
  text "63.00mil (1.600mm)" at 4261,2379.59 h60.27
  text "4" at 5539.99,2379.59 h60.27
  text "PTH" at 5873.55,2379.59 h60.27
  text "Round" at 6133.93,2379.59 h60.27
  text "L1-Top Layer - L4-Bottom Layer" at 7042.43,2379.59 h60.27
  text "241 Total" at 5539.99,2254.6 h60.27
  text "Drill tolerances:" at 4218,2045 h60
  text "For 7.87mil drill via +0/-7.87 mil" at 4312.69,1962 h60
  text "For 10mil drill via +0/-10 mil" at 4312.69,1891.75 h60
  text "For 12mil drill via +0/-12 mil" at 4312.69,1821.5 h60
  text "For PTH  +/-3 mil" at 4312.69,1751.25 h60
  text "For NPTH  +/-2 mil" at 4312.69,1681 h60
  text ".Layer_Name" at -523,-958.49 h60
M17 Embedded Cavity:
  text ".Layer_Name" at -523,-958.49 h60
M18 Embedded Assembly:
  text ".Layer_Name" at -523,-958.49 h60
M19 Embedded Keepout:
  text ".Layer_Name" at -523,-958.49 h60

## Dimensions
0,0 to 2500,0 on M2 Board Dimensions
-1100,-500 to -100,-500 on M2 Board Dimensions
0,2000 to 0,0 on M2 Board Dimensions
